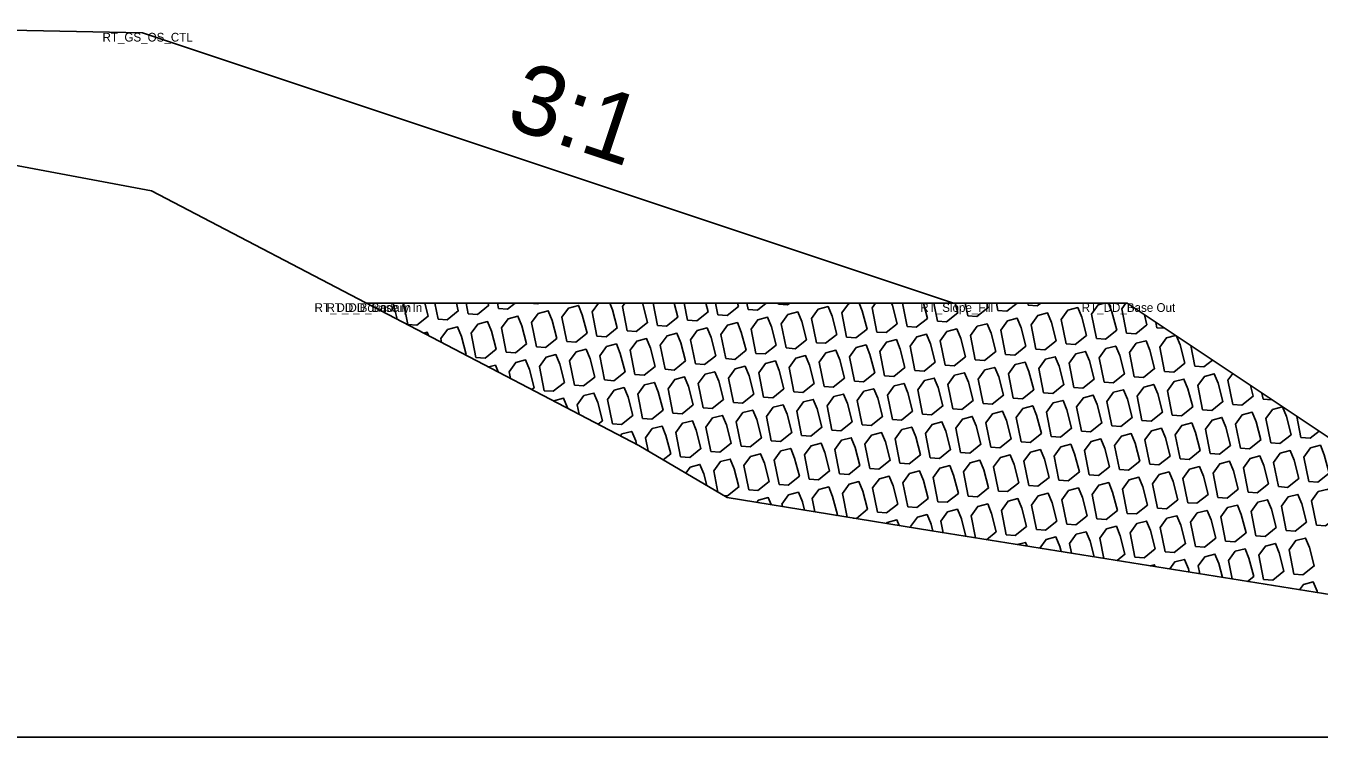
# Model space of a CAD drawing. Extents: x -26 to 203, y -10 to 20020.
# Drawn here: x 115.66 to 130.56, y 2000 to 2008.2 of the extents above; entities that cross this region are included whole.
import ezdxf

# ---------------------------------------------------------------- set-up
doc = ezdxf.new("R2010")
doc.units = 0
for name, color, linetype in [('Default', 7, 'Continuous'), ('Exist Cross Section Cell', 7, 'Continuous'), ('Exist XS Ground Line', 7, 'Continuous'), ('Old_Level_1', 7, 'Continuous'), ('Prop CMT Rip Rap Class II', 7, 'Continuous'), ('Prop CMT Slope Grass', 7, 'Continuous'), ('Prop XS Side Slope Text', 7, 'Continuous')]:
    doc.layers.add(name, color=color, linetype=linetype)

msp = doc.modelspace()

# ---------------------------------------------------------------- linework, layer by layer
at = {"layer": 'Exist Cross Section Cell'}
msp.add_line((100, 2000), (200, 2000), dxfattribs=at)
at = {"layer": 'Exist XS Ground Line'}
for p, q in [((113.876, 2006.898), (117.104, 2006.296)), ((117.104, 2006.296), (122.722, 2003.361)), ((122.722, 2003.361), (123.74, 2002.761)), ((123.74, 2002.761), (126.098, 2002.376)), ((126.098, 2002.376), (133.591, 2001.178))]:
    msp.add_line(p, q, dxfattribs=at)
at = {"layer": 'Old_Level_1'}
for p, q in [((120.009, 2005), (120.058, 2004.754)), ((120.37, 2005), (120.407, 2004.816)), ((120.731, 2005), (120.755, 2004.877)), ((121.092, 2005), (121.104, 2004.939)), ((122.885, 2005), (122.936, 2004.742)), ((123.245, 2005), (123.284, 2004.804)), ((123.606, 2005), (123.633, 2004.865)), ((123.967, 2005), (123.982, 2004.927)), ((124.328, 2005), (124.33, 2004.988)), ((125.76, 2005), (125.813, 2004.73)), ((126.121, 2005), (126.162, 2004.791)), ((126.481, 2005), (126.511, 2004.853)), ((126.842, 2005), (126.859, 2004.914)), ((127.203, 2005), (127.208, 2004.976)), ((128.679, 2004.779), (128.691, 2004.717)), ((128.691, 2004.717), (128.781, 2004.711)), ((129.082, 2004.511), (129.129, 2004.275)), ((129.901, 2003.965), (129.915, 2003.894)), ((129.915, 2003.894), (130.018, 2003.886)), ((130.303, 2003.696), (130.352, 2003.451))]:
    msp.add_line(p, q, dxfattribs=at)
for points in [[(119.673, 2005), (119.654, 2004.973), (119.656, 2004.962)], [(119.937, 2004.815), (119.89, 2004.999), (119.889, 2005)], [(120.058, 2004.754), (120.163, 2004.747), (120.293, 2004.85), (120.254, 2005)], [(120.407, 2004.816), (120.512, 2004.808), (120.641, 2004.911), (120.619, 2005)], [(120.755, 2004.877), (120.861, 2004.87), (120.99, 2004.973), (120.983, 2005)], [(121.104, 2004.939), (121.209, 2004.931), (121.295, 2005)], [(121.457, 2005), (121.558, 2004.993), (121.567, 2005)], [(122.256, 2005), (122.183, 2004.899), (122.239, 2004.619)], [(122.239, 2004.619), (122.344, 2004.612), (122.473, 2004.715), (122.419, 2004.925), (122.388, 2005)], [(122.56, 2005), (122.532, 2004.961), (122.587, 2004.681)], [(122.587, 2004.681), (122.692, 2004.673), (122.822, 2004.776), (122.767, 2004.987), (122.762, 2005)], [(122.936, 2004.742), (123.041, 2004.734), (123.171, 2004.838), (123.129, 2005)], [(123.284, 2004.804), (123.39, 2004.796), (123.519, 2004.899), (123.493, 2005)], [(123.633, 2004.865), (123.738, 2004.857), (123.868, 2004.961), (123.858, 2005)], [(123.982, 2004.927), (124.087, 2004.919), (124.189, 2005)], [(124.33, 2004.988), (124.435, 2004.98), (124.46, 2005)], [(125.164, 2005), (125.138, 2004.993), (125.061, 2004.887), (125.116, 2004.607)], [(125.116, 2004.607), (125.221, 2004.599), (125.351, 2004.702), (125.297, 2004.913), (125.261, 2005)], [(125.447, 2005), (125.409, 2004.948), (125.465, 2004.668)], [(125.465, 2004.668), (125.57, 2004.661), (125.7, 2004.764), (125.645, 2004.974), (125.635, 2005)], [(125.813, 2004.73), (125.919, 2004.722), (126.048, 2004.825), (126.003, 2005)], [(126.162, 2004.791), (126.267, 2004.784), (126.397, 2004.887), (126.368, 2005)], [(126.511, 2004.853), (126.616, 2004.845), (126.745, 2004.948), (126.732, 2005)], [(126.859, 2004.914), (126.964, 2004.907), (127.082, 2005)], [(127.208, 2004.976), (127.313, 2004.968), (127.353, 2005)], [(128.089, 2005), (128.015, 2004.981), (127.938, 2004.874), (127.994, 2004.595)], [(127.994, 2004.595), (128.099, 2004.587), (128.229, 2004.69), (128.174, 2004.901), (128.133, 2005)], [(128.333, 2005), (128.287, 2004.936), (128.342, 2004.656)], [(120.844, 2004.373), (120.949, 2004.366), (121.079, 2004.469), (121.025, 2004.679), (120.979, 2004.789), (120.866, 2004.76), (120.789, 2004.653), (120.844, 2004.373)], [(128.342, 2004.656), (128.448, 2004.648), (128.577, 2004.752), (128.547, 2004.867)], [(120.298, 2004.627), (120.282, 2004.666), (120.242, 2004.656)], [(120.726, 2004.404), (120.73, 2004.407), (120.676, 2004.618), (120.631, 2004.728), (120.517, 2004.698), (120.44, 2004.592), (120.449, 2004.548)], [(128.907, 2004.627), (128.801, 2004.6), (128.724, 2004.493), (128.78, 2004.213)], [(128.78, 2004.213), (128.885, 2004.206), (129.015, 2004.309), (128.96, 2004.52), (128.919, 2004.619)], [(121.489, 2004.005), (121.516, 2004.026), (121.462, 2004.237), (121.417, 2004.347), (121.303, 2004.317), (121.226, 2004.211), (121.241, 2004.134)], [(121.63, 2003.992), (121.735, 2003.985), (121.865, 2004.088), (121.811, 2004.298), (121.765, 2004.408), (121.652, 2004.379), (121.575, 2004.272), (121.63, 2003.992)], [(124.508, 2003.98), (124.613, 2003.972), (124.743, 2004.075), (124.688, 2004.286), (124.643, 2004.396), (124.529, 2004.366), (124.452, 2004.26), (124.508, 2003.98)], [(124.856, 2004.041), (124.962, 2004.034), (125.091, 2004.137), (125.037, 2004.347), (124.992, 2004.457), (124.878, 2004.428), (124.801, 2004.321), (124.856, 2004.041)], [(129.129, 2004.275), (129.234, 2004.267), (129.331, 2004.344)], [(121.1, 2004.208), (121.068, 2004.285), (120.991, 2004.265)], [(123.811, 2003.857), (123.916, 2003.849), (124.045, 2003.952), (123.991, 2004.163), (123.946, 2004.273), (123.832, 2004.243), (123.755, 2004.137), (123.811, 2003.857)], [(124.159, 2003.918), (124.265, 2003.911), (124.394, 2004.014), (124.34, 2004.225), (124.295, 2004.334), (124.181, 2004.305), (124.104, 2004.198), (124.159, 2003.918)], [(129.565, 2004.188), (129.51, 2004.112), (129.566, 2003.832)], [(129.566, 2003.832), (129.671, 2003.825), (129.801, 2003.928), (129.769, 2004.053)], [(121.901, 2003.79), (121.899, 2003.794), (121.854, 2003.904), (121.741, 2003.875), (121.74, 2003.874)], [(122.253, 2003.606), (122.303, 2003.645), (122.248, 2003.856), (122.203, 2003.965), (122.089, 2003.936), (122.012, 2003.83), (122.034, 2003.72)], [(123.202, 2003.23), (123.308, 2003.222), (123.437, 2003.325), (123.383, 2003.536), (123.338, 2003.646), (123.224, 2003.616), (123.147, 2003.51), (123.202, 2003.23)], [(122.696, 2003.374), (122.686, 2003.413), (122.64, 2003.523), (122.527, 2003.493), (122.51, 2003.471)], [(123.002, 2003.195), (123.089, 2003.264), (123.034, 2003.475), (122.989, 2003.584), (122.875, 2003.555), (122.798, 2003.448), (122.828, 2003.298)], [(130.352, 2003.451), (130.457, 2003.443), (130.56, 2003.525)], [(123.703, 2002.783), (123.745, 2002.78), (123.875, 2002.883), (123.82, 2003.093), (123.775, 2003.203), (123.661, 2003.174), (123.584, 2003.067), (123.632, 2002.824)], [(123.506, 2002.899), (123.472, 2003.032), (123.426, 2003.142), (123.313, 2003.112), (123.262, 2003.042)], [(125, 2002.555), (125.009, 2002.563), (124.955, 2002.774), (124.91, 2002.883), (124.796, 2002.854), (124.719, 2002.748), (124.749, 2002.596)], [(125.191, 2002.524), (125.228, 2002.521), (125.358, 2002.625), (125.303, 2002.835), (125.258, 2002.945), (125.145, 2002.916), (125.068, 2002.809), (125.122, 2002.535)], [(124.246, 2002.679), (124.213, 2002.761), (124.099, 2002.731), (124.08, 2002.706)], [(124.631, 2002.616), (124.606, 2002.712), (124.561, 2002.822), (124.447, 2002.793), (124.37, 2002.686), (124.376, 2002.657)], [(126.11, 2002.374), (126.09, 2002.454), (126.044, 2002.564), (125.931, 2002.534), (125.854, 2002.428), (125.856, 2002.415)], [(126.49, 2002.313), (126.438, 2002.516), (126.393, 2002.625), (126.279, 2002.596), (126.202, 2002.489), (126.229, 2002.355)], [(126.727, 2002.275), (126.841, 2002.366), (126.787, 2002.577), (126.742, 2002.687), (126.628, 2002.657), (126.551, 2002.551), (126.602, 2002.295)], [(125.723, 2002.437), (125.696, 2002.502), (125.582, 2002.473), (125.574, 2002.462)], [(128.232, 2002.035), (128.324, 2002.108), (128.27, 2002.319), (128.225, 2002.429), (128.111, 2002.399), (128.034, 2002.293), (128.08, 2002.059)], [(127.588, 2002.138), (127.573, 2002.196), (127.528, 2002.306), (127.414, 2002.276), (127.342, 2002.177)], [(127.968, 2002.077), (127.921, 2002.257), (127.876, 2002.367), (127.763, 2002.338), (127.685, 2002.231), (127.708, 2002.119)], [(127.197, 2002.2), (127.179, 2002.244), (127.081, 2002.219)], [(129.446, 2001.841), (129.405, 2001.999), (129.36, 2002.109), (129.246, 2002.079), (129.169, 2001.973), (129.187, 2001.882)], [(129.737, 2001.794), (129.808, 2001.85), (129.753, 2002.061), (129.708, 2002.17), (129.594, 2002.141), (129.517, 2002.034), (129.559, 2001.823)], [(128.671, 2001.965), (128.662, 2001.986), (128.615, 2001.974)], [(129.065, 2001.901), (129.056, 2001.938), (129.011, 2002.047), (128.897, 2002.018), (128.839, 2001.938)], [(130.543, 2001.665), (130.539, 2001.68), (130.494, 2001.789), (130.38, 2001.76), (130.336, 2001.698)]]:
    msp.add_lwpolyline(points, dxfattribs=at)
for points in [[(121.89, 2004.558), (121.995, 2004.55), (122.125, 2004.653), (122.07, 2004.864), (122.025, 2004.974), (121.911, 2004.944), (121.834, 2004.838)], [(124.768, 2004.545), (124.873, 2004.538), (125.002, 2004.641), (124.948, 2004.852), (124.903, 2004.961), (124.789, 2004.932), (124.712, 2004.825)], [(127.645, 2004.533), (127.751, 2004.525), (127.88, 2004.629), (127.826, 2004.839), (127.78, 2004.949), (127.667, 2004.919), (127.59, 2004.813)], [(121.193, 2004.435), (121.298, 2004.427), (121.428, 2004.53), (121.373, 2004.741), (121.328, 2004.851), (121.214, 2004.821), (121.137, 2004.715)], [(121.541, 2004.496), (121.647, 2004.489), (121.776, 2004.592), (121.722, 2004.802), (121.677, 2004.912), (121.563, 2004.883), (121.486, 2004.776)], [(124.07, 2004.422), (124.176, 2004.415), (124.305, 2004.518), (124.251, 2004.729), (124.206, 2004.838), (124.092, 2004.809), (124.015, 2004.702)], [(124.419, 2004.484), (124.524, 2004.476), (124.654, 2004.579), (124.599, 2004.79), (124.554, 2004.9), (124.44, 2004.87), (124.363, 2004.764)], [(126.948, 2004.41), (127.053, 2004.402), (127.183, 2004.506), (127.128, 2004.716), (127.083, 2004.826), (126.97, 2004.797), (126.892, 2004.69)], [(127.297, 2004.472), (127.402, 2004.464), (127.531, 2004.567), (127.477, 2004.778), (127.432, 2004.887), (127.318, 2004.858), (127.241, 2004.752)], [(123.025, 2004.238), (123.13, 2004.23), (123.259, 2004.334), (123.205, 2004.544), (123.16, 2004.654), (123.046, 2004.624), (122.969, 2004.518)], [(123.373, 2004.3), (123.478, 2004.292), (123.608, 2004.395), (123.554, 2004.606), (123.508, 2004.715), (123.395, 2004.686), (123.318, 2004.579)], [(123.722, 2004.361), (123.827, 2004.353), (123.957, 2004.457), (123.902, 2004.667), (123.857, 2004.777), (123.743, 2004.747), (123.666, 2004.641)], [(125.902, 2004.226), (126.008, 2004.218), (126.137, 2004.321), (126.083, 2004.532), (126.037, 2004.642), (125.924, 2004.612), (125.847, 2004.506)], [(126.251, 2004.287), (126.356, 2004.28), (126.486, 2004.383), (126.431, 2004.593), (126.386, 2004.703), (126.272, 2004.674), (126.195, 2004.567)], [(126.599, 2004.349), (126.705, 2004.341), (126.834, 2004.444), (126.78, 2004.655), (126.735, 2004.764), (126.621, 2004.735), (126.544, 2004.629)], [(122.327, 2004.115), (122.433, 2004.107), (122.562, 2004.211), (122.508, 2004.421), (122.463, 2004.531), (122.349, 2004.502), (122.272, 2004.395)], [(122.676, 2004.177), (122.781, 2004.169), (122.911, 2004.272), (122.856, 2004.483), (122.811, 2004.592), (122.697, 2004.563), (122.62, 2004.457)], [(125.205, 2004.103), (125.31, 2004.095), (125.44, 2004.198), (125.385, 2004.409), (125.34, 2004.519), (125.227, 2004.489), (125.149, 2004.383)], [(125.554, 2004.164), (125.659, 2004.157), (125.788, 2004.26), (125.734, 2004.47), (125.689, 2004.58), (125.575, 2004.551), (125.498, 2004.444)], [(128.083, 2004.09), (128.188, 2004.083), (128.318, 2004.186), (128.263, 2004.397), (128.218, 2004.506), (128.104, 2004.477), (128.027, 2004.37)], [(128.431, 2004.152), (128.537, 2004.144), (128.666, 2004.247), (128.612, 2004.458), (128.567, 2004.568), (128.453, 2004.538), (128.376, 2004.432)], [(121.979, 2004.054), (122.084, 2004.046), (122.214, 2004.149), (122.159, 2004.36), (122.114, 2004.469), (122, 2004.44), (121.923, 2004.334)], [(127.386, 2003.968), (127.491, 2003.96), (127.62, 2004.063), (127.566, 2004.274), (127.521, 2004.383), (127.407, 2004.354), (127.33, 2004.247)], [(127.734, 2004.029), (127.839, 2004.021), (127.969, 2004.125), (127.914, 2004.335), (127.869, 2004.445), (127.756, 2004.415), (127.679, 2004.309)], [(123.462, 2003.795), (123.567, 2003.788), (123.697, 2003.891), (123.642, 2004.102), (123.597, 2004.211), (123.484, 2004.182), (123.406, 2004.075)], [(126.34, 2003.783), (126.445, 2003.775), (126.575, 2003.879), (126.52, 2004.089), (126.475, 2004.199), (126.361, 2004.17), (126.284, 2004.063)], [(126.688, 2003.845), (126.794, 2003.837), (126.923, 2003.94), (126.869, 2004.151), (126.824, 2004.26), (126.71, 2004.231), (126.633, 2004.125)], [(127.037, 2003.906), (127.142, 2003.898), (127.272, 2004.002), (127.217, 2004.212), (127.172, 2004.322), (127.058, 2004.292), (126.981, 2004.186)], [(122.765, 2003.673), (122.87, 2003.665), (123, 2003.768), (122.945, 2003.979), (122.9, 2004.088), (122.786, 2004.059), (122.709, 2003.952)], [(123.113, 2003.734), (123.219, 2003.726), (123.348, 2003.83), (123.294, 2004.04), (123.249, 2004.15), (123.135, 2004.12), (123.058, 2004.014)], [(125.643, 2003.66), (125.748, 2003.653), (125.877, 2003.756), (125.823, 2003.966), (125.778, 2004.076), (125.664, 2004.047), (125.587, 2003.94)], [(125.991, 2003.722), (126.096, 2003.714), (126.226, 2003.817), (126.172, 2004.028), (126.126, 2004.137), (126.013, 2004.108), (125.936, 2004.002)], [(128.52, 2003.648), (128.625, 2003.64), (128.755, 2003.743), (128.701, 2003.954), (128.655, 2004.064), (128.542, 2004.034), (128.465, 2003.928)], [(128.869, 2003.709), (128.974, 2003.702), (129.104, 2003.805), (129.049, 2004.015), (129.004, 2004.125), (128.89, 2004.096), (128.813, 2003.989)], [(129.217, 2003.771), (129.323, 2003.763), (129.452, 2003.866), (129.398, 2004.077), (129.353, 2004.187), (129.239, 2004.157), (129.162, 2004.051)], [(122.416, 2003.611), (122.522, 2003.603), (122.651, 2003.707), (122.597, 2003.917), (122.552, 2004.027), (122.438, 2003.997), (122.361, 2003.891)], [(124.945, 2003.537), (125.051, 2003.53), (125.18, 2003.633), (125.126, 2003.843), (125.081, 2003.953), (124.967, 2003.924), (124.89, 2003.817)], [(125.294, 2003.599), (125.399, 2003.591), (125.529, 2003.694), (125.474, 2003.905), (125.429, 2004.015), (125.315, 2003.985), (125.238, 2003.879)], [(127.823, 2003.525), (127.928, 2003.517), (128.058, 2003.62), (128.003, 2003.831), (127.958, 2003.941), (127.844, 2003.911), (127.767, 2003.805)], [(128.172, 2003.586), (128.277, 2003.579), (128.406, 2003.682), (128.352, 2003.893), (128.307, 2004.002), (128.193, 2003.973), (128.116, 2003.866)], [(123.9, 2003.353), (124.005, 2003.345), (124.134, 2003.448), (124.08, 2003.659), (124.035, 2003.769), (123.921, 2003.739), (123.844, 2003.633)], [(124.248, 2003.414), (124.353, 2003.407), (124.483, 2003.51), (124.429, 2003.72), (124.383, 2003.83), (124.27, 2003.801), (124.193, 2003.694)], [(124.597, 2003.476), (124.702, 2003.468), (124.832, 2003.571), (124.777, 2003.782), (124.732, 2003.892), (124.618, 2003.862), (124.541, 2003.756)], [(126.777, 2003.34), (126.882, 2003.333), (127.012, 2003.436), (126.958, 2003.647), (126.912, 2003.756), (126.799, 2003.727), (126.722, 2003.62)], [(127.126, 2003.402), (127.231, 2003.394), (127.361, 2003.498), (127.306, 2003.708), (127.261, 2003.818), (127.147, 2003.788), (127.07, 2003.682)], [(127.474, 2003.463), (127.58, 2003.456), (127.709, 2003.559), (127.655, 2003.77), (127.61, 2003.879), (127.496, 2003.85), (127.419, 2003.743)], [(130.003, 2003.39), (130.109, 2003.382), (130.238, 2003.485), (130.184, 2003.696), (130.139, 2003.805), (130.025, 2003.776), (129.948, 2003.67)], [(123.551, 2003.291), (123.656, 2003.284), (123.786, 2003.387), (123.731, 2003.598), (123.686, 2003.707), (123.572, 2003.678), (123.495, 2003.571)], [(126.08, 2003.218), (126.185, 2003.21), (126.315, 2003.313), (126.26, 2003.524), (126.215, 2003.633), (126.101, 2003.604), (126.024, 2003.498)], [(126.429, 2003.279), (126.534, 2003.271), (126.663, 2003.375), (126.609, 2003.585), (126.564, 2003.695), (126.45, 2003.665), (126.373, 2003.559)], [(128.958, 2003.205), (129.063, 2003.198), (129.192, 2003.301), (129.138, 2003.511), (129.093, 2003.621), (128.979, 2003.592), (128.902, 2003.485)], [(129.306, 2003.267), (129.412, 2003.259), (129.541, 2003.362), (129.487, 2003.573), (129.441, 2003.683), (129.328, 2003.653), (129.251, 2003.547)], [(129.655, 2003.328), (129.76, 2003.321), (129.89, 2003.424), (129.835, 2003.634), (129.79, 2003.744), (129.676, 2003.715), (129.599, 2003.608)], [(125.034, 2003.033), (125.14, 2003.026), (125.269, 2003.129), (125.215, 2003.339), (125.169, 2003.449), (125.056, 2003.42), (124.979, 2003.313)], [(125.383, 2003.095), (125.488, 2003.087), (125.618, 2003.19), (125.563, 2003.401), (125.518, 2003.51), (125.404, 2003.481), (125.327, 2003.375)], [(125.731, 2003.156), (125.837, 2003.148), (125.966, 2003.252), (125.912, 2003.462), (125.867, 2003.572), (125.753, 2003.543), (125.676, 2003.436)], [(128.26, 2003.082), (128.366, 2003.075), (128.495, 2003.178), (128.441, 2003.388), (128.396, 2003.498), (128.282, 2003.469), (128.205, 2003.362)], [(128.609, 2003.144), (128.714, 2003.136), (128.844, 2003.239), (128.789, 2003.45), (128.744, 2003.56), (128.631, 2003.53), (128.553, 2003.424)], [(124.337, 2002.91), (124.442, 2002.903), (124.572, 2003.006), (124.517, 2003.216), (124.472, 2003.326), (124.359, 2003.297), (124.281, 2003.19)], [(124.686, 2002.972), (124.791, 2002.964), (124.92, 2003.067), (124.866, 2003.278), (124.821, 2003.388), (124.707, 2003.358), (124.63, 2003.252)], [(127.215, 2002.898), (127.32, 2002.89), (127.45, 2002.993), (127.395, 2003.204), (127.35, 2003.314), (127.236, 2003.284), (127.159, 2003.178)], [(127.563, 2002.959), (127.669, 2002.952), (127.798, 2003.055), (127.744, 2003.266), (127.699, 2003.375), (127.585, 2003.346), (127.508, 2003.239)], [(127.912, 2003.021), (128.017, 2003.013), (128.147, 2003.116), (128.092, 2003.327), (128.047, 2003.437), (127.933, 2003.407), (127.856, 2003.301)], [(130.092, 2002.886), (130.198, 2002.878), (130.327, 2002.981), (130.273, 2003.192), (130.228, 2003.301), (130.114, 2003.272), (130.037, 2003.166)], [(130.441, 2002.947), (130.546, 2002.939), (130.676, 2003.043), (130.621, 2003.253), (130.576, 2003.363), (130.462, 2003.333), (130.385, 2003.227)], [(123.988, 2002.849), (124.094, 2002.841), (124.223, 2002.944), (124.169, 2003.155), (124.124, 2003.265), (124.01, 2003.235), (123.933, 2003.129)], [(126.518, 2002.775), (126.623, 2002.767), (126.752, 2002.871), (126.698, 2003.081), (126.653, 2003.191), (126.539, 2003.161), (126.462, 2003.055)], [(126.866, 2002.836), (126.971, 2002.829), (127.101, 2002.932), (127.046, 2003.143), (127.001, 2003.252), (126.888, 2003.223), (126.81, 2003.116)], [(129.395, 2002.763), (129.5, 2002.755), (129.63, 2002.858), (129.576, 2003.069), (129.53, 2003.178), (129.417, 2003.149), (129.34, 2003.043)], [(129.744, 2002.824), (129.849, 2002.816), (129.979, 2002.92), (129.924, 2003.13), (129.879, 2003.24), (129.765, 2003.211), (129.688, 2003.104)], [(125.472, 2002.591), (125.577, 2002.583), (125.707, 2002.686), (125.652, 2002.897), (125.607, 2003.006), (125.493, 2002.977), (125.416, 2002.871)], [(125.82, 2002.652), (125.926, 2002.644), (126.055, 2002.748), (126.001, 2002.958), (125.956, 2003.068), (125.842, 2003.038), (125.765, 2002.932)], [(126.169, 2002.713), (126.274, 2002.706), (126.404, 2002.809), (126.349, 2003.02), (126.304, 2003.129), (126.19, 2003.1), (126.113, 2002.993)], [(128.698, 2002.64), (128.803, 2002.632), (128.933, 2002.735), (128.878, 2002.946), (128.833, 2003.056), (128.719, 2003.026), (128.642, 2002.92)], [(129.047, 2002.701), (129.152, 2002.694), (129.281, 2002.797), (129.227, 2003.007), (129.182, 2003.117), (129.068, 2003.088), (128.991, 2002.981)], [(127.652, 2002.455), (127.757, 2002.448), (127.887, 2002.551), (127.833, 2002.761), (127.787, 2002.871), (127.674, 2002.842), (127.597, 2002.735)], [(128.001, 2002.517), (128.106, 2002.509), (128.236, 2002.612), (128.181, 2002.823), (128.136, 2002.933), (128.022, 2002.903), (127.945, 2002.797)], [(128.349, 2002.578), (128.455, 2002.571), (128.584, 2002.674), (128.53, 2002.884), (128.485, 2002.994), (128.371, 2002.965), (128.294, 2002.858)], [(130.53, 2002.443), (130.635, 2002.435), (130.765, 2002.539), (130.71, 2002.749), (130.665, 2002.859), (130.551, 2002.829), (130.474, 2002.723)], [(126.955, 2002.332), (127.06, 2002.325), (127.19, 2002.428), (127.135, 2002.639), (127.09, 2002.748), (126.976, 2002.719), (126.899, 2002.612)], [(127.304, 2002.394), (127.409, 2002.386), (127.538, 2002.489), (127.484, 2002.7), (127.439, 2002.81), (127.325, 2002.78), (127.248, 2002.674)], [(129.833, 2002.32), (129.938, 2002.312), (130.067, 2002.416), (130.013, 2002.626), (129.968, 2002.736), (129.854, 2002.706), (129.777, 2002.6)], [(130.181, 2002.381), (130.287, 2002.374), (130.416, 2002.477), (130.362, 2002.688), (130.316, 2002.797), (130.203, 2002.768), (130.126, 2002.661)], [(129.135, 2002.197), (129.241, 2002.189), (129.37, 2002.293), (129.316, 2002.503), (129.271, 2002.613), (129.157, 2002.584), (129.08, 2002.477)], [(129.484, 2002.259), (129.589, 2002.251), (129.719, 2002.354), (129.664, 2002.565), (129.619, 2002.674), (129.505, 2002.645), (129.428, 2002.539)], [(128.438, 2002.074), (128.544, 2002.067), (128.673, 2002.17), (128.619, 2002.38), (128.573, 2002.49), (128.46, 2002.461), (128.383, 2002.354)], [(128.787, 2002.136), (128.892, 2002.128), (129.022, 2002.231), (128.967, 2002.442), (128.922, 2002.551), (128.808, 2002.522), (128.731, 2002.416)], [(130.27, 2001.877), (130.375, 2001.87), (130.505, 2001.973), (130.45, 2002.184), (130.405, 2002.293), (130.292, 2002.264), (130.215, 2002.157)], [(129.922, 2001.816), (130.027, 2001.808), (130.156, 2001.912), (130.102, 2002.122), (130.057, 2002.232), (129.943, 2002.202), (129.866, 2002.096)]]:
    msp.add_lwpolyline(points, close=True, dxfattribs=at)
at = {"layer": 'Prop CMT Rip Rap Class II'}
for points in [[(119.584, 2005), (119.584, 2005)], [(119.584, 2005), (128.348, 2005), (134.029, 2001.212)]]:
    msp.add_lwpolyline(points, dxfattribs=at)
at = {"layer": 'Prop CMT Slope Grass'}
msp.add_lwpolyline([(113, 2008.195), (117, 2008.115), (126.347, 2005)], dxfattribs=at)

# ---------------------------------------------------------------- texts
at = {"layer": 'Default'}
for s, p in [('RT_GS_OS_CTL', (116.54, 2008.015)), ('RT_DD_Boundary In', (118.984, 2004.9)), ('RT_DD_Base In', (119.122, 2004.9)), ('RT_Slope_Fill', (125.965, 2004.9)), ('RT_DD_Base Out', (127.825, 2004.9))]:
    msp.add_text(s, height=0.1, dxfattribs=at).set_placement(p)
at = {"layer": 'Prop XS Side Slope Text'}
msp.add_text('3:1', height=0.8, rotation=341.5668, dxfattribs=at).set_placement((121.167, 2007.043))

doc.saveas('drawing.dxf')
